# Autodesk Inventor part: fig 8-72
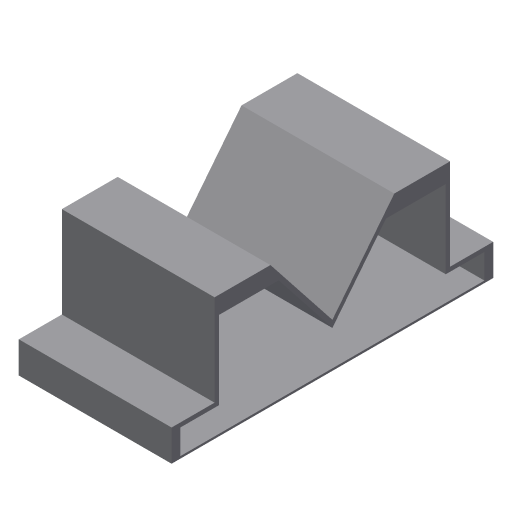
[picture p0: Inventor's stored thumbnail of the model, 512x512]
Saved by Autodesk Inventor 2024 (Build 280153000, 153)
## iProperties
Shininess: 77.0
Length Units: 11269
Angle Units: 11279
Time Units: 11290
Mass Units: 11283
Length Display Precision: 3
Angle Display Precision: 2
Created: 2002-01
Part Number: fig 8-72
Document SubType Name: Modeling
Designer: ***
Density: 1 g/cm^3
Material: Generic
Appearance: Default
Density: 0.0
Volumn: 0.0
Area: 0.0
PropertySet Name: Model Information
Control State: 0
Master: False
Checked Out: False
Author: ***
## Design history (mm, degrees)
sketch "Sketch2"
  geometry: L1 (0, 0)-(-14.184, 17.961); L2 (-14.184, 17.961)-(-26.987, 17.961); L3 (-26.987, 17.961)-(-26.987, -2.947); L4 (-26.987, -2.947)-(-36.842, -2.947); L5 (-36.842, -2.947)-(-36.842, -10.132); L6 (26.987, 17.961)-(26.987, -2.947); L7 (14.184, 17.961)-(26.987, 17.961); L8 (26.987, -2.947)-(36.842, -2.947); L9 (36.842, -10.132)-(-36.842, -10.132); L10 (36.842, -2.947)-(36.842, -10.132); L11 (0, 0)-(14.184, 17.961)
  constraints: 22 end point, 2 horizontal, 2 parallel, 1 perpendicular
extrude "Extrusion1" new body sketch "Sketch2" distance "d0" = 35; taper "d1" = 0 deg
shell "Shell3" dims "d8" = 4, "d9" = 4, "d10" = 2, "d11" = 2, "d12" = 0.5, "d13" = 1
body "Solid1"
node "Sketch1"
